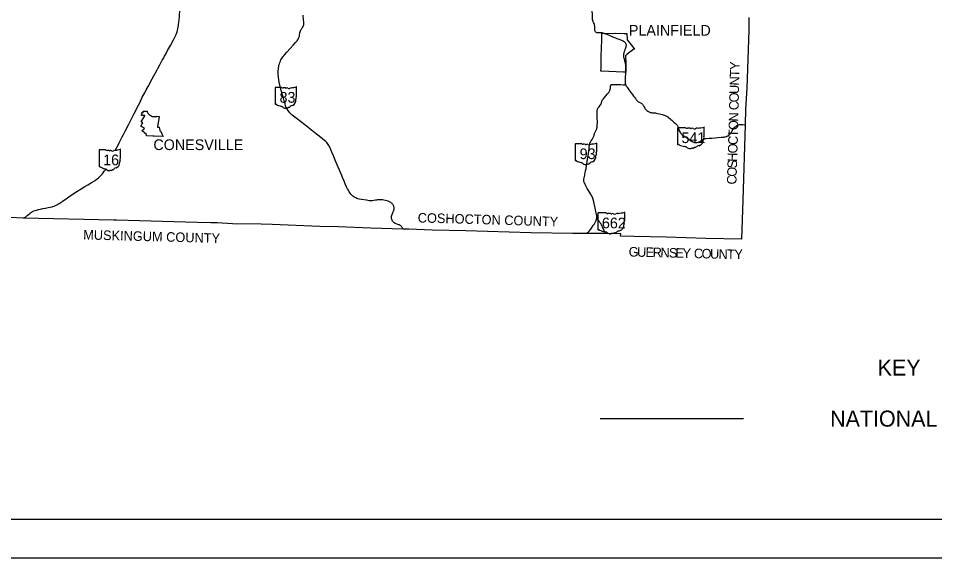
# Model space of a CAD drawing. Extents: x 2004415 to 2276415, y 751181 to 927181.
# Drawn here: x 2124487 to 2220435, y 751181 to 807649 of the extents above; entities that cross this region are included whole.
import ezdxf

# ---------------------------------------------------------------- set-up
doc = ezdxf.new("R2010")
doc.units = 0
for name, color, linetype in [('Default', 7, 'Continuous'), ('GM_X_Corporation', 7, 'Continuous'), ('GM_X_Corporation_Text', 7, 'Continuous'), ('GM_X_County', 7, 'Continuous'), ('GM_X_County_Text', 7, 'Continuous'), ('GM_X_State_Location', 7, 'Continuous'), ('GM_X_State_Route', 7, 'Continuous'), ('GM_X_State_Shield', 7, 'Continuous'), ('SH_Border', 7, 'Continuous'), ('SH_Cut_Line', 7, 'Continuous'), ('UT_P_Electric', 7, 'Continuous')]:
    doc.layers.add(name, color=color, linetype=linetype)

msp = doc.modelspace()

# ---------------------------------------------------------------- linework, layer by layer
at = {"layer": 'GM_X_Corporation'}
for points in [[(2188202, 806076), (2188226, 805385), (2188802, 804717), (2188942, 804541), (2189054, 804450), (2188964, 804448), (2188196, 803855), (2188072, 803729), (2188061, 803514), (2188113, 803240), (2188099, 802359), (2188083, 802010), (2187853, 802017), (2185559, 802104), (2185485, 802109), (2185490, 802165), (2185498, 802416), (2185528, 803463), (2185557, 804719), (2185559, 804771), (2185568, 805116), (2185574, 805266), (2185576, 805326), (2185581, 805536), (2185589, 805879), (2185591, 805947), (2185596, 806107), (2185831, 806102), (2186692, 806078), (2186962, 806079), (2186976, 806079), (2187930, 806077), (2188038, 806076)], [(2137335, 796341), (2137347, 796404), (2137358, 796429), (2137378, 796476), (2137383, 796489), (2137415, 796556), (2137443, 796601), (2137519, 796723), (2137498, 796736), (2137358, 796821), (2137731, 797432), (2137747, 797459), (2137536, 797465), (2137398, 797468), (2137403, 797663), (2137405, 797775), (2137550, 797772), (2137559, 797934), (2137973, 797928), (2137993, 797868), (2138004, 797778), (2138004, 797776), (2138057, 797722), (2138123, 797653), (2138178, 797597), (2138298, 797503), (2138360, 797440), (2138367, 797433), (2138397, 797432), (2138490, 797373), (2138610, 797383), (2138881, 797371), (2138973, 797369), (2138979, 797405), (2139168, 797377), (2139254, 797365), (2139249, 797337), (2139247, 797327), (2139245, 797321), (2139071, 796322), (2139062, 796267), (2139234, 796259), (2139232, 796219), (2139281, 796092), (2139313, 796027), (2139300, 795858), (2139349, 795854), (2139382, 795853), (2139525, 795567), (2139650, 795287), (2139659, 795267), (2138727, 795316), (2138572, 795313), (2137922, 795345), (2137912, 795486), (2137467, 795854), (2137447, 795870), (2137464, 795888), (2137521, 795948), (2137554, 795983), (2137564, 795993), (2137653, 796088), (2137683, 796115), (2137611, 796190), (2137480, 796257)]]:
    msp.add_lwpolyline(points, close=True, dxfattribs=at)
at = {"layer": 'GM_X_County'}
msp.add_lwpolyline([(2200976, 807730), (2200976, 807629), (2200975, 807541), (2200976, 807471), (2200980, 807397), (2200985, 807329), (2200988, 807267), (2200988, 807202), (2200988, 807107), (2200989, 807027), (2200986, 806939), (2200984, 806875), (2200988, 806732), (2200989, 806696), (2200991, 806637), (2200991, 806584), (2200992, 806538), (2200989, 806420), (2200752, 800346), (2200640, 798126), (2200607, 796487), (2200352, 788594), (2200213, 784515), (2196471, 784613), (2192356, 784732), (2188969, 784801), (2187543, 784833), (2187559, 785091), (2185988, 785114), (2184041, 785134), (2182507, 785112), (2178155, 785189), (2171358, 785391), (2167834, 785463), (2165393, 785569), (2164756, 785563), (2161402, 785685), (2158022, 785823), (2156064, 785864), (2151050, 786066), (2149915, 786091), (2146903, 786142), (2145320, 786224), (2144635, 786226), (2143204, 786275), (2134773, 786503), (2134471, 786517), (2125039, 786734), (2123596, 786788)], dxfattribs=at)
at = {"layer": 'GM_X_State_Route'}
for p, q in [((2186452, 805810), (2186370, 805844)), ((2186527, 805780), (2186452, 805810)), ((2186603, 805750), (2186527, 805780)), ((2186849, 805649), (2186603, 805750)), ((2187279, 805476), (2187180, 805513)), ((2184048, 792669), (2184079, 792888))]:
    msp.add_line(p, q, dxfattribs=at)
for points in [[(2164757, 785560), (2164733, 785632), (2164709, 785684), (2164671, 785748), (2164634, 785804), (2164592, 785857), (2164532, 785910), (2164454, 785966), (2164357, 786019), (2164216, 786074), (2164058, 786127), (2163939, 786180), (2163843, 786240), (2163746, 786326), (2163674, 786422), (2163616, 786530), (2163584, 786625), (2163565, 786704), (2163556, 786783), (2163559, 786862), (2163570, 786948), (2163593, 787037), (2163623, 787122), (2163700, 787319), (2163765, 787465), (2163808, 787581), (2163829, 787671), (2163834, 787752), (2163829, 787826), (2163814, 787909), (2163794, 787985), (2163763, 788060), (2163725, 788131), (2163676, 788200), (2163630, 788253), (2163563, 788312), (2163486, 788366), (2163407, 788409), (2163292, 788460), (2163203, 788495), (2163083, 788536), (2162924, 788577), (2162764, 788609), (2162635, 788629), (2162510, 788637), (2162418, 788640), (2162225, 788642), (2162109, 788633), (2161998, 788622), (2161889, 788603), (2161695, 788566), (2161566, 788543), (2161513, 788538), (2161370, 788534), (2161230, 788550), (2160944, 788594), (2160414, 788678), (2160167, 788721), (2160049, 788752), (2159937, 788789), (2159822, 788840), (2159729, 788888), (2159633, 788948), (2159515, 789032), (2159420, 789119), (2159314, 789238), (2159227, 789352), (2159138, 789486), (2159043, 789648), (2158955, 789815), (2158861, 790019), (2158724, 790332), (2158606, 790603), (2158441, 790998), (2158355, 791194), (2157985, 792060), (2157663, 792816), (2157482, 793240), (2157317, 793624), (2157235, 793814), (2157094, 794149), (2157039, 794262), (2156992, 794350), (2156927, 794450), (2156862, 794541), (2156786, 794633), (2156684, 794745), (2156536, 794875), (2156302, 795062), (2155724, 795516), (2154491, 796490), (2153587, 797203), (2153177, 797526), (2152905, 797764), (2152804, 797881), (2152727, 797987), (2152633, 798134), (2152567, 798256), (2152513, 798379), (2152470, 798497), (2152417, 798680), (2152325, 799012), (2152252, 799276), (2152149, 799653), (2152084, 799883), (2152022, 800107), (2151939, 800400), (2151847, 800746), (2151795, 800993), (2151765, 801161), (2151748, 801282), (2151733, 801423), (2151722, 801530), (2151708, 801778), (2151705, 801911), (2151700, 802105), (2151712, 802357), (2151731, 802497), (2151753, 802619), (2151780, 802736), (2151819, 802875), (2151873, 803034), (2151922, 803160), (2151988, 803299), (2152061, 803432), (2152178, 803612), (2152272, 803737), (2152389, 803879), (2152599, 804108), (2152944, 804482), (2153274, 804843), (2153526, 805109), (2153680, 805282), (2153751, 805383), (2153798, 805459), (2153869, 805630), (2153913, 805775), (2153941, 805935), (2153973, 806120), (2153999, 806227), (2154032, 806333), (2154075, 806429), (2154131, 806527), (2154220, 806645), (2154279, 806729), (2154323, 806814), (2154358, 806907), (2154383, 807013), (2154392, 807138), (2154383, 807286), (2154359, 807509), (2154321, 807969)], [(2184692, 807267), (2184668, 807324), (2184639, 807415), (2184619, 807519), (2184610, 807647), (2184602, 807958), (2184594, 808142), (2184573, 808322), (2184548, 808458), (2184511, 808588), (2184474, 808706)], [(2184863, 806354), (2184857, 806389), (2184850, 806443), (2184847, 806599), (2184838, 806821), (2184828, 806908), (2184808, 806999), (2184769, 807092), (2184716, 807210), (2184692, 807267)], [(2185714, 806102), (2185699, 806107), (2185630, 806121), (2185533, 806133), (2185412, 806135), (2185211, 806132), (2185120, 806137), (2185068, 806148), (2185016, 806173), (2184961, 806210), (2184925, 806243), (2184885, 806302), (2184863, 806354)], [(2186012, 805993), (2185796, 806077), (2185714, 806102)], [(2186370, 805844), (2186131, 805943), (2186012, 805993)], [(2187180, 805513), (2187049, 805569), (2186849, 805649)], [(2187421, 805416), (2187284, 805474), (2187279, 805476)], [(2187935, 805197), (2187861, 805235), (2187741, 805287), (2187421, 805416)], [(2188145, 804740), (2188153, 804795), (2188152, 804858), (2188132, 804941), (2188097, 805019), (2188063, 805079), (2188004, 805143), (2187935, 805197)], [(2187933, 803455), (2187905, 803598), (2187891, 803710), (2187890, 803824), (2187898, 803923), (2187910, 803998), (2187936, 804115), (2187976, 804230), (2188037, 804396)], [(2188037, 804396), (2188138, 804673), (2188145, 804740)], [(2188037, 803048), (2188033, 803064), (2188005, 803166), (2187981, 803261), (2187960, 803338), (2187944, 803403), (2187933, 803455)], [(2188090, 802790), (2188077, 802869), (2188056, 802969), (2188037, 803048)], [(2188088, 802058), (2188089, 802105), (2188094, 802242), (2188099, 802518), (2188100, 802656), (2188094, 802769), (2188090, 802790)], [(2188060, 800796), (2188054, 800838), (2188054, 800936), (2188054, 800960), (2188055, 801010), (2188063, 801246), (2188070, 801441), (2188085, 801884), (2188088, 802058)], [(2184079, 792888), (2184111, 793089), (2184138, 793267), (2184208, 793724), (2184247, 793986), (2184254, 794031), (2184267, 794156), (2184282, 794321), (2184294, 794419), (2184312, 794500), (2184344, 794604), (2184384, 794684), (2184472, 794834), (2184557, 794970), (2184641, 795112), (2184713, 795243), (2184748, 795325), (2184772, 795395), (2184791, 795480), (2184816, 795580), (2184842, 795649), (2184875, 795727), (2184905, 795796), (2184988, 795957), (2185048, 796079), (2185072, 796156), (2185090, 796238), (2185100, 796337), (2185111, 796540), (2185114, 796703), (2185116, 796884), (2185103, 797125), (2185092, 797405), (2185088, 797522), (2185094, 797721), (2185099, 797884), (2185112, 798050), (2185121, 798116), (2185136, 798166), (2185165, 798228), (2185206, 798288), (2185299, 798397), (2185422, 798540), (2185489, 798644), (2185522, 798722), (2185541, 798786), (2185558, 798887), (2185572, 798949), (2185593, 799008), (2185628, 799075), (2185684, 799143), (2185762, 799229), (2185870, 799358), (2186005, 799535), (2186189, 799750), (2186301, 799900), (2186389, 800038), (2186415, 800089), (2186439, 800147), (2186454, 800203), (2186470, 800261), (2186478, 800337), (2186494, 800510), (2186504, 800588), (2186516, 800631), (2186538, 800669), (2186569, 800703), (2186613, 800728), (2186680, 800738), (2186805, 800738), (2187220, 800720), (2187583, 800704), (2187818, 800691), (2187946, 800693), (2187982, 800704), (2188016, 800727), (2188037, 800758), (2188060, 800796)], [(2188060, 800796), (2188067, 800744), (2188085, 800684), (2188107, 800632), (2188140, 800560), (2188176, 800500), (2188225, 800428), (2188296, 800328), (2188419, 800165), (2188618, 799901), (2188783, 799681), (2188914, 799504), (2188998, 799387), (2189093, 799257), (2189151, 799180), (2189207, 799105), (2189257, 799048), (2189301, 799006), (2189360, 798956), (2189428, 798908), (2189494, 798868), (2189632, 798807), (2189691, 798778), (2189743, 798747), (2189792, 798709), (2189844, 798662), (2189894, 798602), (2189941, 798526), (2189985, 798435), (2190027, 798342), (2190074, 798250), (2190133, 798160), (2190216, 798063), (2190303, 797984), (2190390, 797921), (2190457, 797883), (2190522, 797851), (2190597, 797819), (2190662, 797799), (2190752, 797780), (2190869, 797768), (2191001, 797766), (2191089, 797761), (2191195, 797746), (2191275, 797731), (2191421, 797698), (2191625, 797649), (2191900, 797582), (2192022, 797549), (2192132, 797516), (2192289, 797452), (2192396, 797391), (2192480, 797340), (2192572, 797272), (2192726, 797140), (2192823, 797054), (2192902, 796985), (2193025, 796876), (2193129, 796784), (2193284, 796645), (2193375, 796563), (2193415, 796523), (2193461, 796464), (2193503, 796405), (2193540, 796350), (2193572, 796283), (2193598, 796212), (2193621, 796109), (2193644, 795996), (2193663, 795923), (2193694, 795853), (2193739, 795760), (2193809, 795657), (2193861, 795592), (2193909, 795545), (2193975, 795489), (2194069, 795422), (2194117, 795388), (2194249, 795299), (2194552, 795090), (2194868, 794874), (2194949, 794818), (2195041, 794754), (2195117, 794713), (2195195, 794681), (2195261, 794661), (2195335, 794646), (2195418, 794639), (2195489, 794639), (2195564, 794648), (2195660, 794673), (2195725, 794698), (2195790, 794731), (2195830, 794757), (2195937, 794832), (2196030, 794895), (2196109, 794938), (2196194, 794979), (2196282, 795013), (2196374, 795039), (2196443, 795051), (2196511, 795061), (2196808, 795086), (2197095, 795109), (2197451, 795144), (2197730, 795168), (2198069, 795194), (2198362, 795219), (2198442, 795230), (2198504, 795245), (2198623, 795280), (2198734, 795330), (2198853, 795396), (2198923, 795452), (2198991, 795522), (2199054, 795597), (2199106, 795671), (2199151, 795745), (2199218, 795858), (2199297, 795990), (2199372, 796095), (2199442, 796181), (2199533, 796275), (2199633, 796361), (2199720, 796419), (2199797, 796465), (2199890, 796505), (2200008, 796535), (2200109, 796545), (2200217, 796544), (2200349, 796528), (2200506, 796504), (2200608, 796484)], [(2185051, 786832), (2185051, 786876), (2185047, 786942), (2185045, 786995), (2185027, 787099), (2184992, 787263), (2184918, 787587), (2184836, 787944), (2184768, 788262), (2184734, 788421), (2184681, 788675), (2184657, 788778), (2184633, 788864), (2184602, 788932), (2184541, 789044), (2184387, 789279), (2184180, 789620), (2184060, 789818), (2183946, 790045), (2183850, 790246), (2183744, 790483), (2183710, 790574), (2183693, 790648), (2183690, 790724), (2183697, 790804), (2183729, 790944), (2183792, 791212), (2183821, 791332), (2183848, 791470), (2183886, 791667), (2183930, 791908), (2183977, 792199), (2184048, 792669)], [(2184042, 785132), (2184127, 785222), (2184231, 785334), (2184302, 785417), (2184371, 785502), (2184440, 785592), (2184490, 785670), (2184559, 785772), (2184619, 785862), (2184683, 785956), (2184728, 786025), (2184767, 786080), (2184839, 786190), (2184883, 786265), (2184925, 786331), (2184948, 786384), (2184969, 786434), (2184989, 786486), (2185003, 786529), (2185018, 786583), (2185032, 786645), (2185045, 786733), (2185051, 786818), (2185051, 786832)], [(2185989, 785111), (2185968, 785136), (2185944, 785171), (2185920, 785208), (2185897, 785253), (2185833, 785402), (2185746, 785604), (2185671, 785777), (2185611, 785920), (2185565, 786021), (2185531, 786084), (2185497, 786136), (2185470, 786177), (2185418, 786243), (2185387, 786284), (2185341, 786339), (2185296, 786396), (2185219, 786495), (2185159, 786566), (2185112, 786624), (2185077, 786672), (2185066, 786688), (2185045, 786733)]]:
    msp.add_lwpolyline(points, dxfattribs=at)
at = {"layer": 'GM_X_State_Shield'}
for p, q in [((2151381, 800392), (2151381, 798691)), ((2152059, 800421), (2151403, 800421)), ((2153622, 799573), (2153622, 800463)), ((2153622, 799574), (2153622, 799573)), ((2193508, 796171), (2193508, 794470)), ((2194356, 796201), (2193536, 796201)), ((2196310, 795353), (2196310, 796243)), ((2182805, 794490), (2182805, 792789)), ((2183484, 794520), (2182827, 794520)), ((2185047, 793672), (2185047, 794562)), ((2196310, 795353), (2196310, 795353)), ((2132935, 793850), (2132935, 792148)), ((2133614, 793879), (2132957, 793879)), ((2135177, 793031), (2135177, 793921)), ((2185046, 793672), (2185047, 793672)), ((2135176, 793031), (2135177, 793031)), ((2185175, 787242), (2185175, 785541)), ((2186023, 787272), (2185202, 787272)), ((2187976, 786424), (2187976, 787314)), ((2187976, 786424), (2187976, 786424))]:
    msp.add_line(p, q, dxfattribs=at)
for centre, radius, start, end in [((2151407, 800396), 26, 98.1301, 188.1301), ((2152216, 800619), 252, 231.61951, 271.11188), ((2152299, 799466), 904, 80.48669, 94.98827), ((2152505, 800404), 72.7, 219.79206, 297.10237), ((2152611, 800208), 151, 54.46668, 119.14113), ((2152806, 800477), 182, 233.85621, 294.82819), ((2153127, 799902), 478, 97.34618, 120.76885), ((2152824, 802740), 2377, 275.84447, 288.90645), ((2153598, 800467), 25, 351.86209, 97.738), ((2153712, 799201), 169, 136.8065, 186.92959), ((2153617, 799508), 38.6, 107.94398, 210.33697), ((2153371, 799396), 232, 340.03296, 23.64957), ((2153596, 799570), 26.7, 289.60381, 7.73413), ((2151407, 798687), 26.2, 171.95839, 258.30661), ((2151411, 798861), 200, 267.33899, 280.60386), ((2151452, 798593), 72.1, 29.74838, 93.27175), ((2152362, 800121), 1716, 240.41292, 257.1985), ((2151850, 797926), 537, 47.18416, 75.83597), ((2152431, 798584), 341, 230.70037, 286.29184), ((2152653, 798457), 182, 268.77702, 315.54927), ((2152817, 798292), 51.1, 65.75173, 132.64842), ((2152795, 798526), 192, 282.87319, 323.27711), ((2153208, 798213), 326, 94.40312, 142.57675), ((2152957, 799088), 595, 292.30889, 8.98584), ((2152628, 797996), 280, 85.69512, 111.20995), ((2182831, 794494), 26, 98.1301, 188.1301), ((2183640, 794717), 252, 231.61951, 271.11188), ((2183724, 793565), 904, 80.48669, 94.98827), ((2183929, 794503), 72.7, 219.79206, 297.10237), ((2184036, 794306), 151, 54.46668, 119.14113), ((2184551, 794000), 478, 97.34618, 120.76885), ((2184248, 796839), 2377, 275.84447, 288.90645), ((2185022, 794565), 25, 351.86209, 97.738), ((2132961, 793853), 26, 98.1301, 188.1301), ((2133770, 794076), 252, 231.61951, 271.11188), ((2133853, 792924), 904, 80.48669, 94.98827), ((2134059, 793862), 72.7, 219.79206, 297.10237), ((2134165, 793665), 151, 54.46668, 119.14113), ((2134360, 793935), 182, 233.85621, 294.82819), ((2134681, 793359), 478, 97.34618, 120.76885), ((2134378, 796198), 2377, 275.84447, 288.90645), ((2135152, 793925), 25, 351.86209, 97.738), ((2184230, 794576), 182, 233.85621, 294.82819), ((2185041, 793607), 38.6, 107.94398, 210.33697), ((2184795, 793494), 232, 340.03296, 23.64957), ((2185020, 793668), 26.7, 289.60381, 7.73413), ((2134511, 792546), 595, 292.30889, 8.98584), ((2135266, 792659), 169, 136.8065, 186.92959), ((2135171, 792966), 38.6, 107.94398, 210.33697), ((2134925, 792853), 232, 340.03296, 23.64957), ((2135150, 793028), 26.7, 289.60381, 7.73413), ((2182831, 792785), 26.2, 171.95839, 258.30661), ((2182835, 792960), 200, 267.33899, 280.60386), ((2182876, 792691), 72.1, 29.74838, 93.27175), ((2183786, 794219), 1716, 240.41292, 257.1985), ((2183274, 792025), 537, 47.18416, 75.83597), ((2184632, 792312), 326, 94.40312, 142.57675), ((2184381, 793186), 595, 292.30889, 8.98584), ((2185136, 793299), 169, 136.8065, 186.92959), ((2132961, 792145), 26.2, 171.95839, 258.30661), ((2132965, 792319), 200, 267.33899, 280.60386), ((2133006, 792050), 72.1, 29.74838, 93.27175), ((2133916, 793579), 1716, 240.41292, 257.1985), ((2133404, 791384), 537, 47.18416, 75.83597), ((2133985, 792042), 341, 230.70037, 286.29184), ((2134182, 791454), 280, 85.69512, 111.20995), ((2134207, 791914), 182, 268.77702, 315.54927), ((2134371, 791750), 51.1, 65.75173, 132.64842), ((2134349, 791984), 192, 282.87319, 323.27711), ((2134762, 791671), 326, 94.40312, 142.57675), ((2183855, 792683), 341, 230.70037, 286.29184), ((2184052, 792094), 280, 85.69512, 111.20995), ((2184077, 792555), 182, 268.77702, 315.54927), ((2184241, 792390), 51.1, 65.75173, 132.64842), ((2184220, 792624), 192, 282.87319, 323.27711)]:
    msp.add_arc(centre, radius, start, end, dxfattribs=at)
for centre, major_axis, start_param, end_param in [((2193540, 796175), (32.5, 0), 1.712693, 3.28349), ((2194552, 796398), (315, 0), 4.042523, 4.731795), ((2194656, 795246), (1130, 0), 1.404758, 1.657858), ((2194913, 796184), (90.8, 0), 3.836095, 5.185415), ((2195046, 795987), (189, 0), 0.950623, 2.079405), ((2195290, 796257), (227, 0), 4.081561, 5.145723), ((2195691, 795681), (598, 0), 1.699011, 2.107814), ((2195312, 798520), (2971, 0), 4.814394, 5.042369), ((2196279, 796247), (31.2, 0), 6.141152, 7.989035), ((2193541, 794466), (32.7, 0), 3.00124, 4.508301), ((2195479, 794867), (743, 0), 5.101752, 6.440018), ((2196422, 794980), (211, 0), 2.387724, 3.262537), ((2196303, 795288), (48.3, 0), 1.883978, 3.671073), ((2195996, 795175), (290, 0), 5.934695, 6.695948), ((2196277, 795349), (33.4, 0), 5.05454, 6.418171), ((2193546, 794641), (250, 0), 4.665946, 4.897461), ((2193597, 794372), (90.1, 0), 0.519207, 1.627899), ((2194734, 795900), (2146, 0), 4.195997, 4.488961), ((2194095, 793706), (671, 0), 0.823519, 1.323587), ((2194821, 794364), (426, 0), 4.026481, 4.996735), ((2195067, 793775), (350, 0), 1.495662, 1.94098), ((2195098, 794236), (227, 0), 4.691044, 5.507374), ((2195303, 794071), (63.9, 0), 1.147584, 2.315152), ((2195276, 794305), (240, 0), 4.937069, 5.64225), ((2195792, 793993), (407, 0), 1.647645, 2.488434), ((2185207, 787246), (32.5, 0), 1.712693, 3.28349), ((2186218, 787469), (315, 0), 4.042523, 4.731795), ((2186322, 786317), (1130, 0), 1.404758, 1.657858), ((2186579, 787255), (90.8, 0), 3.836095, 5.185415), ((2186712, 787058), (189, 0), 0.950623, 2.079405), ((2186956, 787328), (227, 0), 4.081561, 5.145723), ((2187357, 786752), (598, 0), 1.699011, 2.107814), ((2186978, 789591), (2971, 0), 4.814394, 5.042369), ((2187945, 787318), (31.2, 0), 6.141152, 7.989035), ((2187145, 785938), (743, 0), 5.101752, 6.440018), ((2188088, 786052), (211, 0), 2.387724, 3.262537), ((2187969, 786359), (48.3, 0), 1.883978, 3.671073), ((2187662, 786246), (290, 0), 5.934695, 6.695948), ((2187943, 786421), (33.4, 0), 5.05454, 6.418171), ((2185207, 785538), (32.7, 0), 3.00124, 4.508301), ((2185212, 785712), (250, 0), 4.665946, 4.897461), ((2185263, 785443), (90.1, 0), 0.519207, 1.627899), ((2186401, 786972), (2146, 0), 4.195997, 4.488961), ((2185761, 784777), (671, 0), 0.823519, 1.323587), ((2186487, 785435), (426, 0), 4.026481, 4.996735), ((2186733, 784847), (350, 0), 1.495662, 1.94098), ((2186764, 785307), (227, 0), 4.691044, 5.507374), ((2186970, 785143), (63.9, 0), 1.147584, 2.315152), ((2186942, 785376), (240, 0), 4.937069, 5.64225), ((2187458, 785064), (407, 0), 1.647645, 2.488434)]:
    msp.add_ellipse(centre, major_axis=major_axis, ratio=0.8, start_param=start_param, end_param=end_param, dxfattribs=at)
at = {"layer": 'SH_Border'}
msp.add_lwpolyline([(2016415, 923181), (2272415, 923181), (2272415, 755181), (2016415, 755181)], close=True, dxfattribs=at)
at = {"layer": 'SH_Cut_Line'}
msp.add_lwpolyline([(2004415, 751181), (2276415, 751181), (2276415, 927181), (2004415, 927181)], close=True, dxfattribs=at)
at = {"layer": 'UT_P_Electric'}
msp.add_line((2185405, 765741), (2200405, 765741), dxfattribs=at)
for points in [[(2140838, 805598), (2140918, 805750), (2140988, 805897), (2141025, 805984), (2141075, 806120), (2141112, 806237), (2141157, 806402), (2141186, 806552), (2141215, 806726), (2141278, 807231), (2141348, 807808), (2141378, 808083), (2141394, 808299), (2141399, 808560), (2141395, 808710), (2141387, 808956), (2141368, 809244), (2141353, 809549), (2141333, 809859), (2141312, 810236), (2141287, 810641), (2141271, 810900), (2141233, 811535), (2141205, 812029)], [(2135003, 794516), (2135058, 794624), (2135160, 794829), (2135363, 795226), (2135493, 795477), (2135665, 795821), (2136016, 796506), (2136217, 796906), (2136432, 797326), (2136587, 797625), (2136817, 798084), (2136925, 798298), (2137193, 798816), (2137470, 799378), (2137717, 799849), (2137876, 800154), (2138066, 800504), (2138507, 801321), (2138854, 801960), (2139011, 802242), (2139097, 802406), (2139310, 802795), (2139380, 802923), (2139565, 803261), (2139674, 803457), (2139790, 803674), (2139952, 803974), (2140108, 804268), (2140407, 804806), (2140741, 805413), (2140838, 805598)], [(2134657, 793838), (2134678, 793879), (2135003, 794516)], [(2128952, 788378), (2128956, 788381), (2129121, 788497), (2129500, 788760), (2129788, 788961), (2130218, 789261), (2130596, 789513), (2131062, 789793), (2131452, 790026), (2131758, 790212), (2132214, 790484), (2132455, 790631), (2132571, 790713), (2132731, 790829), (2132873, 790947), (2133011, 791074), (2133153, 791216), (2133254, 791329), (2133376, 791480), (2133488, 791631), (2133581, 791766), (2133642, 791866)], [(2125041, 786731), (2125150, 786795), (2125220, 786839), (2125272, 786876), (2125332, 786921), (2125419, 786995), (2125561, 787118), (2125649, 787196), (2125754, 787284), (2125862, 787360), (2125964, 787421), (2126099, 787482), (2126246, 787529), (2126404, 787577), (2126597, 787632), (2126794, 787677), (2127056, 787729), (2127300, 787776), (2127336, 787783)], [(2127336, 787783), (2127618, 787837), (2127816, 787877), (2128013, 787923), (2128116, 787954), (2128248, 788000), (2128368, 788047), (2128503, 788110), (2128630, 788175), (2128753, 788248), (2128952, 788378)]]:
    msp.add_lwpolyline(points, dxfattribs=at)

# ---------------------------------------------------------------- texts
at = {"layer": 'Default'}
for s, p in [('KEY', (2214470, 770248)), ('NATIONAL HIGHWAY SYSTEM (NHS)', (2209485, 764901))]:
    msp.add_text(s, height=1680, dxfattribs=at).set_placement(p)
at = {"layer": 'GM_X_Corporation_Text'}
for s, p in [('PLAINFIELD', (2188416, 805833)), ('CONESVILLE', (2138630, 793857))]:
    msp.add_text(s, height=1120, rotation=0.00001, dxfattribs=at).set_placement(p)
at = {"layer": 'GM_X_County_Text'}
for s, rotation, p in [('Y', 88.63575, (2199998, 802228)), ('T', 88.63575, (2199980, 801482)), ('N', 88.63727, (2199959, 800599)), ('U', 88.63684, (2199938, 799717)), ('O', 88.64992, (2199918, 798835)), ('C', 88.73764, (2199900, 798020)), ('N', 88.96217, (2199878, 796833)), ('O', 88.46902, (2199854, 795941)), ('T', 88.21262, (2199831, 795190)), ('O', 88.15834, (2199776, 793492)), ('C', 88.16164, (2199804, 794374)), ('H', 88.15937, (2199748, 792610)), ('S', 88.15904, (2199726, 791931)), ('O', 88.15939, (2199698, 791048)), ('C', 88.15938, (2199671, 790234)), ('COSHOCTON COUNTY', 358.37379, (2166297, 786281)), ('MUSKINGUM COUNTY', 358.45973, (2131266, 784504)), ('G', 358.54165, (2188380, 782718)), ('U', 358.54223, (2189264, 782696)), ('E', 358.54188, (2190148, 782673)), ('R', 358.54156, (2190896, 782654)), ('N', 358.54273, (2191710, 782633)), ('S', 358.54084, (2192594, 782611)), ('E', 358.54233, (2193271, 782594)), ('Y', 358.54165, (2194019, 782575)), ('C', 358.54134, (2195207, 782544)), ('O', 358.54145, (2196021, 782524)), ('U', 358.54205, (2196905, 782501)), ('N', 358.54464, (2197789, 782479)), ('T', 358.7696, (2198677, 782456)), ('Y', 1.32265, (2199474, 782440))]:
    msp.add_text(s, height=1000, rotation=rotation, dxfattribs=at).set_placement(p)
at = {"layer": 'GM_X_State_Location'}
for s, p in [('541', (2194548, 794691)), ('16', (2133789, 792579)), ('93', (2183949, 793459)), ('83', (2158605, 789838)), ('662', (2185242, 785772))]:
    msp.add_text(s, height=1, rotation=0.00001, dxfattribs=at).set_placement(p)
for s, p in [('s', (2194902, 794764)), ('r', (2194901, 794764)), ('s', (2184201, 793532)), ('r', (2184201, 793532)), ('s', (2134041, 792652)), ('r', (2134041, 792652)), ('s', (2158857, 789911)), ('r', (2158857, 789911)), ('s', (2185596, 785845)), ('r', (2185595, 785845))]:
    msp.add_text(s, height=1, dxfattribs=at).set_placement(p)
at = {"layer": 'GM_X_State_Shield'}
for s, p in [('83', (2151837, 798811)), ('541', (2193921, 794590)), ('93', (2183261, 792909)), ('16', (2133373, 792268)), ('662', (2185591, 785661))]:
    msp.add_text(s, height=1120.7, dxfattribs=at).set_placement(p)

doc.saveas('drawing.dxf')
